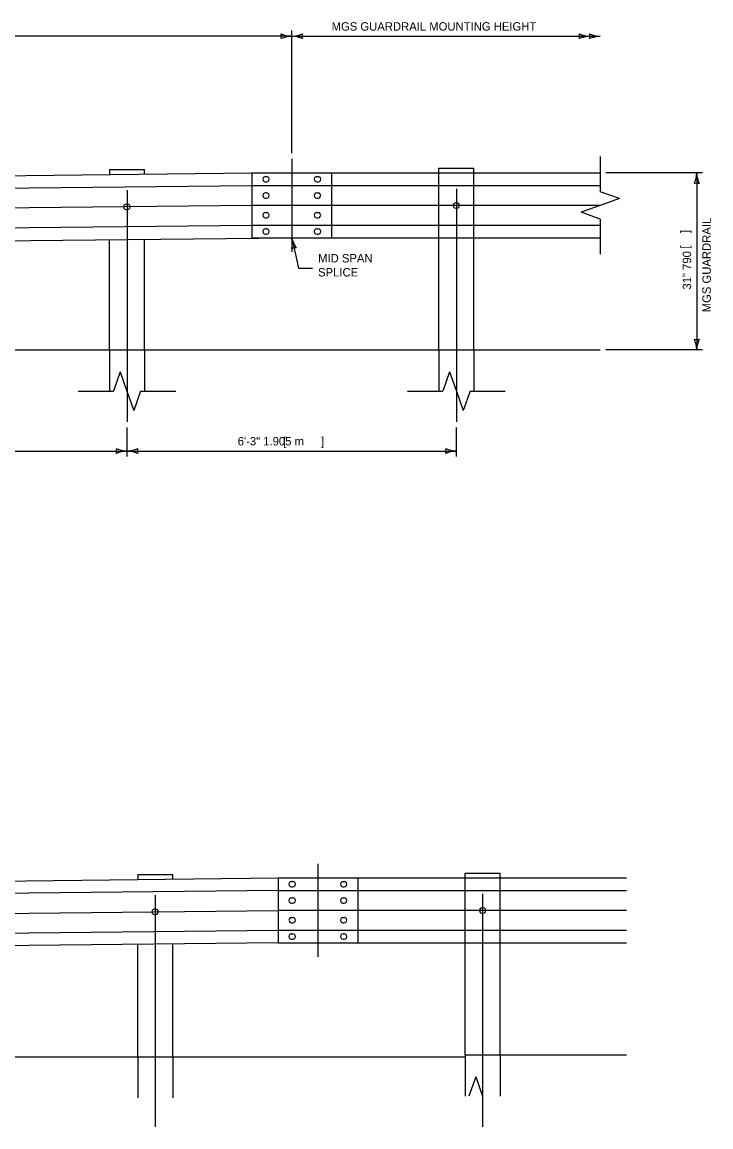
# Model space of a CAD drawing. Extents: x 49991.4 to 50070, y 49987.6 to 50011.4.
# Drawn here: x 50040.78 to 50045.69, y 50001.89 to 50009.76 of the extents above; entities that cross this region are included whole.
import ezdxf

# ---------------------------------------------------------------- set-up
doc = ezdxf.new("R2010")
doc.units = 0
for name, color, linetype in [('Level 1', 7, 'Continuous'), ('Level 2', 7, 'Continuous'), ('Level 3', 7, 'Continuous'), ('Level 4', 7, 'Continuous'), ('Level 5', 7, 'Continuous'), ('Level 6', 7, 'Continuous')]:
    doc.layers.add(name, color=color, linetype=linetype)

msp = doc.modelspace()

# ---------------------------------------------------------------- linework, layer by layer
at = {"layer": 'Level 1'}
for p, q in [((50041.4063, 50008.709), (50041.4063, 50008.6732)), ((50041.4063, 50008.709), (50041.6562, 50008.709)), ((50041.6562, 50008.676), (50041.6562, 50008.709)), ((50043.7513, 50008.6845), (50043.7513, 50008.7177)), ((50043.7513, 50008.7177), (50044.0012, 50008.7177)), ((50044.0012, 50008.6845), (50044.0012, 50008.7177)), ((50033.0587, 50008.5806), (50042.4211, 50008.6845)), ((50042.4211, 50008.6845), (50042.421, 50008.3131)), ((50042.4211, 50008.6845), (50044.9011, 50008.6845)), ((50042.5163, 50008.6583), (50042.5254, 50008.6583)), ((50042.5163, 50008.6206), (50042.5254, 50008.6206)), ((50042.8824, 50008.6583), (50042.8915, 50008.6583)), ((50042.8824, 50008.6205), (50042.8915, 50008.6205)), ((50033.0587, 50008.5015), (50042.4211, 50008.5945)), ((50042.4211, 50008.5945), (50044.9011, 50008.5945)), ((50042.5163, 50008.543), (50042.5254, 50008.543)), ((50042.8822, 50008.5429), (50042.8913, 50008.5429)), ((50041.5251, 50008.4623), (50041.5342, 50008.4623)), ((50042.5163, 50008.5052), (50042.5254, 50008.5052)), ((50042.8822, 50008.5052), (50042.8913, 50008.5052)), ((50043.8717, 50008.4725), (50043.8808, 50008.4725)), ((50041.5251, 50008.4246), (50041.5342, 50008.4246)), ((50042.5165, 50008.4023), (50042.5256, 50008.4023)), ((50042.8822, 50008.4022), (50042.8913, 50008.4022)), ((50043.8717, 50008.4348), (50043.8808, 50008.4348)), ((50033.0586, 50008.2092), (50042.421, 50008.3131)), ((50042.421, 50008.3131), (50042.421, 50008.2231)), ((50042.421, 50008.3131), (50044.9011, 50008.3131)), ((50042.5165, 50008.3646), (50042.5256, 50008.3646)), ((50042.8822, 50008.3645), (50042.8913, 50008.3645)), ((50033.0586, 50008.1192), (50042.7021, 50008.2231)), ((50042.421, 50008.2231), (50044.9011, 50008.2231)), ((50042.5163, 50008.2869), (50042.5254, 50008.2869)), ((50042.5163, 50008.2492), (50042.5254, 50008.2492)), ((50042.8824, 50008.2869), (50042.8915, 50008.2869)), ((50042.8824, 50008.2491), (50042.8915, 50008.2491)), ((50043.7513, 50007.4243), (50043.7513, 50008.2231)), ((50044.0013, 50007.4243), (50044.0013, 50008.2231)), ((50041.4063, 50007.4243), (50041.4063, 50008.2091)), ((50041.656, 50007.4243), (50041.656, 50008.2118)), ((50034.514, 50007.4243), (50043.7513, 50007.4243)), ((50044.0013, 50007.4243), (50044.9012, 50007.4243)), ((50032.0738, 50003.5478), (50042.608, 50003.6646)), ((50041.6075, 50003.6893), (50041.6075, 50003.6535)), ((50041.6075, 50003.6893), (50041.8574, 50003.6893)), ((50041.8574, 50003.6563), (50041.8574, 50003.6893)), ((50042.608, 50003.6646), (50045.088, 50003.6646)), ((50042.608, 50003.6646), (50042.608, 50003.2932)), ((50043.9383, 50003.6646), (50043.9383, 50003.6978)), ((50043.9383, 50003.6978), (50044.1882, 50003.6978)), ((50044.1882, 50003.6646), (50044.1882, 50003.6978)), ((50042.7033, 50003.6385), (50042.7124, 50003.6385)), ((50042.7033, 50003.6007), (50042.7124, 50003.6007)), ((50043.0693, 50003.6384), (50043.0784, 50003.6384)), ((50043.0693, 50003.6007), (50043.0784, 50003.6007)), ((50042.608, 50003.5746), (50032.0738, 50003.4686)), ((50042.608, 50003.5746), (50045.088, 50003.5746)), ((50042.7033, 50003.5231), (50042.7124, 50003.5231)), ((50043.0691, 50003.523), (50043.0782, 50003.523)), ((50041.7263, 50003.4426), (50041.7354, 50003.4426)), ((50042.7033, 50003.4854), (50042.7124, 50003.4854)), ((50043.0691, 50003.4853), (50043.0782, 50003.4853)), ((50044.0586, 50003.4526), (50044.0677, 50003.4526)), ((50041.7263, 50003.4049), (50041.7354, 50003.4049)), ((50042.7035, 50003.3824), (50042.7125, 50003.3824)), ((50042.7035, 50003.3447), (50042.7125, 50003.3447)), ((50043.0691, 50003.3824), (50043.0782, 50003.3824)), ((50043.0691, 50003.3446), (50043.0782, 50003.3446)), ((50044.0586, 50003.4149), (50044.0677, 50003.4149)), ((50032.0737, 50003.1764), (50042.608, 50003.2932)), ((50042.608, 50003.2932), (50042.608, 50003.2032)), ((50042.608, 50003.2932), (50045.088, 50003.2932)), ((50042.7032, 50003.2671), (50042.7123, 50003.2671)), ((50043.0694, 50003.267), (50043.0785, 50003.267)), ((50042.608, 50003.2032), (50032.0737, 50003.0864)), ((50041.6075, 50002.3915), (50041.6075, 50003.1921)), ((50041.8572, 50002.3915), (50041.8572, 50003.1949)), ((50042.608, 50003.2032), (50045.088, 50003.2032)), ((50042.7032, 50003.2293), (50042.7123, 50003.2293)), ((50043.0694, 50003.2293), (50043.0785, 50003.2293)), ((50043.9382, 50002.4045), (50043.9382, 50003.2032)), ((50044.1882, 50002.4045), (50044.1882, 50003.2032)), ((50044.1882, 50002.4045), (50045.0881, 50002.4045)), ((50033.5291, 50002.3915), (50043.9383, 50002.3915))]:
    msp.add_line(p, q, dxfattribs=at)
for centre, start_param, end_param in [((50042.5163, 50008.6395), 4.712389, 7.853982), ((50042.5254, 50008.6395), 1.570796, 4.712389), ((50042.8824, 50008.6394), 4.712389, 7.853982), ((50042.8915, 50008.6394), 1.570796, 4.712389), ((50042.5163, 50008.5241), 4.712389, 7.853982), ((50042.5254, 50008.5241), 1.570796, 4.712389), ((50042.8822, 50008.524), 4.712389, 7.853982), ((50042.8913, 50008.524), 1.570796, 4.712389), ((50041.5251, 50008.4434), 4.712389, 7.853982), ((50041.5342, 50008.4434), 1.570796, 4.712389), ((50043.8717, 50008.4536), 4.712389, 7.853982), ((50043.8808, 50008.4536), 1.570796, 4.712389), ((50042.5165, 50008.3834), 4.712389, 7.853982), ((50042.5256, 50008.3834), 1.570796, 4.712389), ((50042.8822, 50008.3834), 4.712389, 7.853982), ((50042.8913, 50008.3834), 1.570796, 4.712389), ((50042.5163, 50008.2681), 4.712389, 7.853982), ((50042.5254, 50008.2681), 1.570796, 4.712389), ((50042.8824, 50008.268), 4.712389, 7.853982), ((50042.8915, 50008.268), 1.570796, 4.712389), ((50042.7033, 50003.6196), 4.712389, 7.853982), ((50042.7124, 50003.6196), 1.570796, 4.712389), ((50043.0693, 50003.6195), 4.712389, 7.853982), ((50043.0784, 50003.6195), 1.570796, 4.712389), ((50042.7033, 50003.5042), 4.712389, 7.853982), ((50042.7124, 50003.5042), 1.570796, 4.712389), ((50043.0691, 50003.5042), 4.712389, 7.853982), ((50043.0782, 50003.5042), 1.570796, 4.712389), ((50041.7263, 50003.4237), 4.712389, 7.853982), ((50041.7354, 50003.4237), 1.570796, 4.712389), ((50044.0586, 50003.4338), 4.712389, 7.853982), ((50044.0677, 50003.4338), 1.570796, 4.712389), ((50042.7035, 50003.3636), 4.712389, 7.853982), ((50042.7125, 50003.3636), 1.570796, 4.712389), ((50043.0691, 50003.3635), 4.712389, 7.853982), ((50043.0782, 50003.3635), 1.570796, 4.712389), ((50042.7032, 50003.2482), 4.712389, 7.853982), ((50042.7123, 50003.2482), 1.570796, 4.712389), ((50043.0694, 50003.2481), 4.712389, 7.853982), ((50043.0785, 50003.2481), 1.570796, 4.712389)]:
    msp.add_ellipse(centre, major_axis=(-0.0189, 0), ratio=0.998676, start_param=start_param, end_param=end_param, dxfattribs=at)
at = {"layer": 'Level 2'}
for p, q in [((50043.7513, 50008.2231), (50043.7513, 50008.6839)), ((50044.0013, 50008.2231), (50044.0013, 50008.6839)), ((50043.7513, 50007.4243), (50044.0013, 50007.4243)), ((50043.9382, 50003.2032), (50043.9382, 50003.664)), ((50044.1882, 50003.2032), (50044.1882, 50003.664)), ((50043.9382, 50002.4045), (50044.1882, 50002.4045))]:
    msp.add_line(p, q, dxfattribs=at)
at = {"layer": 'Level 3'}
for p, q in [((50042.7039, 50009.658), (50033.3414, 50009.658)), ((50042.7039, 50008.8245), (50042.7039, 50009.698)), ((50042.7039, 50009.658), (50044.901, 50009.658)), ((50045.6277, 50008.6845), (50044.9411, 50008.6845)), ((50045.5877, 50008.6845), (50045.5878, 50007.4243)), ((50045.6278, 50007.4243), (50044.9412, 50007.4243)), ((50041.5313, 50006.6646), (50041.5313, 50006.8719)), ((50043.8764, 50006.6646), (50043.8764, 50006.8719)), ((50039.1952, 50006.7046), (50041.5313, 50006.7046)), ((50041.5313, 50006.7046), (50043.8764, 50006.7046))]:
    msp.add_line(p, q, dxfattribs=at)
msp.add_lwpolyline([(50042.7038, 50008.2231), (50042.7518, 50008.0076), (50042.8518, 50008.0076)], dxfattribs=at)
for centre, radius, start, end in [((50042.7131, 50009.8801), 0.2223, 247.45601, 267.63952), ((50042.5757, 50009.658), 0.0548, 342.13882, 17.86118), ((50042.7154, 50009.4252), 0.233, 92.82731, 112.07716), ((50042.6924, 50009.8907), 0.233, 272.82731, 292.07716), ((50042.6947, 50009.4358), 0.2223, 67.45601, 87.63952), ((50042.8321, 50009.658), 0.0548, 162.13882, 197.86118), ((50044.8367, 50009.8801), 0.2223, 247.45601, 267.63952), ((50044.6993, 50009.658), 0.0548, 342.13882, 17.86118), ((50044.8391, 50009.4252), 0.233, 92.82731, 112.07716), ((50044.9102, 50009.8801), 0.2223, 247.45601, 267.63952), ((50044.7728, 50009.658), 0.0548, 342.13882, 17.86118), ((50044.9125, 50009.4252), 0.233, 92.82731, 112.07716), ((50045.3656, 50008.6936), 0.2223, 337.45601, 357.63952), ((50045.8204, 50008.696), 0.233, 182.82731, 202.07716), ((50045.5877, 50008.5563), 0.0548, 72.13882, 107.86118), ((50042.485, 50008.1838), 0.2223, 349.99985, 10.18335), ((50042.9285, 50008.2848), 0.233, 195.37115, 214.621), ((50042.7317, 50008.0979), 0.0548, 84.68265, 120.40502), ((50045.5878, 50007.5525), 0.0548, 252.13882, 287.86118), ((50045.3551, 50007.4128), 0.233, 2.82731, 22.07716), ((50045.8099, 50007.4152), 0.2223, 157.45601, 177.63952), ((50041.5405, 50006.9268), 0.2223, 247.45601, 267.63952), ((50041.4031, 50006.7046), 0.0548, 342.13882, 17.86118), ((50041.5405, 50006.9268), 0.2223, 247.45601, 267.63952), ((50041.4031, 50006.7046), 0.0548, 342.13882, 17.86118), ((50041.5428, 50006.4719), 0.233, 92.82731, 112.07716), ((50041.5428, 50006.4719), 0.233, 92.82731, 112.07716), ((50041.5198, 50006.9374), 0.233, 272.82731, 292.07716), ((50041.5198, 50006.9374), 0.233, 272.82731, 292.07716), ((50041.5221, 50006.4825), 0.2223, 67.45601, 87.63952), ((50041.5221, 50006.4825), 0.2223, 67.45601, 87.63952), ((50041.6595, 50006.7046), 0.0548, 162.13882, 197.86118), ((50041.6595, 50006.7046), 0.0548, 162.13882, 197.86118), ((50043.8855, 50006.9268), 0.2223, 247.45601, 267.63952), ((50043.7481, 50006.7046), 0.0548, 342.13882, 17.86118), ((50043.8855, 50006.9268), 0.2223, 247.45601, 267.63952), ((50043.7481, 50006.7046), 0.0548, 342.13882, 17.86118), ((50043.8879, 50006.4719), 0.233, 92.82731, 112.07716), ((50043.8879, 50006.4719), 0.233, 92.82731, 112.07716)]:
    msp.add_arc(centre, radius, start, end, dxfattribs=at)
at = {"layer": 'Level 4'}
for p, q in [((50042.9868, 50008.6845), (50042.9868, 50008.2231)), ((50041.4063, 50007.4243), (50041.4063, 50007.1313)), ((50041.656, 50007.4243), (50041.656, 50007.1313)), ((50043.7513, 50007.4243), (50043.7513, 50007.1313)), ((50044.0013, 50007.4243), (50044.0013, 50007.1313)), ((50043.1737, 50003.6646), (50043.1737, 50003.2032)), ((50043.9382, 50002.4045), (50043.9382, 50002.1114)), ((50044.1882, 50002.4045), (50044.1882, 50002.1114)), ((50041.6075, 50002.3915), (50041.6075, 50002.0984)), ((50041.8572, 50002.3915), (50041.8572, 50002.0984))]:
    msp.add_line(p, q, dxfattribs=at)
at = {"layer": 'Level 5'}
for p, q in [((50042.7039, 50008.7845), (50042.7039, 50008.1228)), ((50041.5313, 50008.5623), (50041.5313, 50006.9119)), ((50043.8764, 50008.5725), (50043.8764, 50006.9119)), ((50042.4211, 50008.4536), (50033.0587, 50008.3498)), ((50044.9011, 50008.4536), (50042.4211, 50008.4536)), ((50042.8908, 50003.7646), (50042.8908, 50003.1029)), ((50041.7325, 50003.5426), (50041.7325, 50001.8922)), ((50044.0633, 50003.5526), (50044.0633, 50001.892)), ((50032.0738, 50003.3169), (50042.608, 50003.4338)), ((50045.088, 50003.4338), (50042.608, 50003.4338))]:
    msp.add_line(p, q, dxfattribs=at)
at = {"layer": 'Level 6'}
for p, q in [((50044.901, 50008.8008), (50044.901, 50008.5508)), ((50045.0383, 50008.5023), (50044.901, 50008.5508)), ((50045.0383, 50008.5023), (50044.901, 50008.4535)), ((50044.901, 50008.4535), (50044.764, 50008.405)), ((50044.901, 50008.3563), (50044.764, 50008.405)), ((50044.901, 50008.3563), (50044.901, 50008.1063)), ((50041.4824, 50007.2685), (50041.4339, 50007.1313)), ((50041.4824, 50007.2685), (50041.5311, 50007.1313)), ((50043.8275, 50007.2685), (50043.779, 50007.1313)), ((50043.8275, 50007.2685), (50043.8763, 50007.1313)), ((50041.1839, 50007.1313), (50041.4339, 50007.1313)), ((50041.5311, 50007.1313), (50041.5796, 50006.9943)), ((50041.6284, 50007.1313), (50041.5796, 50006.9943)), ((50041.6284, 50007.1313), (50041.8784, 50007.1313)), ((50043.529, 50007.1313), (50043.779, 50007.1313)), ((50043.8763, 50007.1313), (50043.9248, 50006.9943)), ((50043.9735, 50007.1313), (50043.9248, 50006.9943)), ((50043.9735, 50007.1313), (50044.2235, 50007.1313)), ((50044.0144, 50002.2487), (50043.9659, 50002.1114)), ((50044.0144, 50002.2487), (50044.0632, 50002.1114))]:
    msp.add_line(p, q, dxfattribs=at)

# ---------------------------------------------------------------- texts
at = {"layer": 'Level 2'}
for s, p in [('MGS GUARDRAIL MOUNTING HEIGHT', (50042.9878, 50009.698)), ('MID SPAN', (50042.8918, 50008.0475)), ('SPLICE', (50042.8918, 50007.9476)), ('6\'-3" 1.905 m', (50042.3193, 50006.7446)), ('[           ]', (50042.6444, 50006.7442))]:
    msp.add_text(s, height=0.06, dxfattribs=at).set_placement(p)
for s, rotation, p in [('MGS GUARDRAIL', 90, (50045.6878, 50007.6924)), ('[    ]', 270, (50045.4877, 50008.2797)), ('31" 790', 90, (50045.5478, 50007.8543))]:
    msp.add_text(s, height=0.06, rotation=rotation, dxfattribs=at).set_placement(p)

doc.saveas('drawing.dxf')
